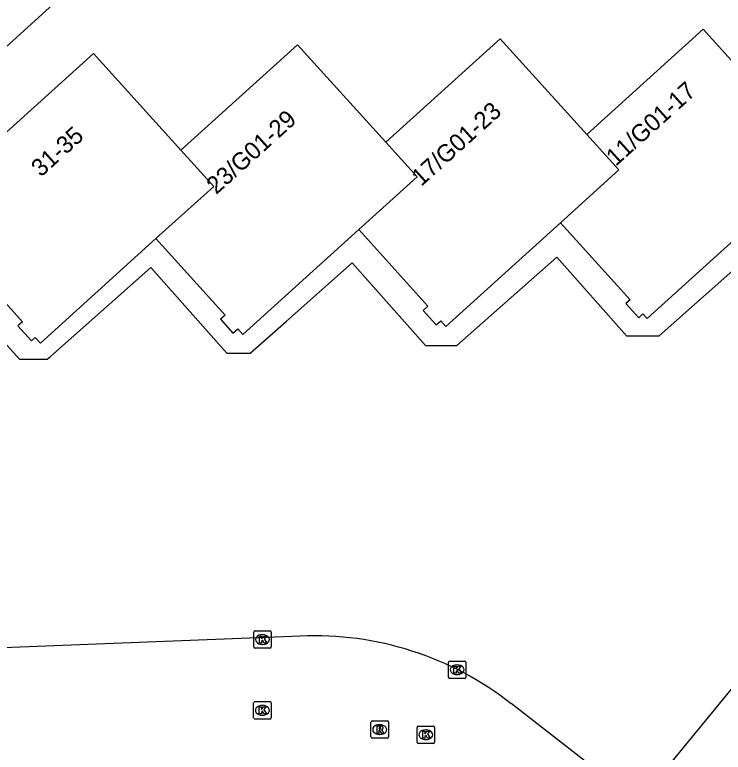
# Model space of a CAD drawing. Extents: x 160356 to 161355, y 381727 to 382845.
# Drawn here: x 160896.38 to 160937.12, y 382011.19 to 382053.61 of the extents above; entities that cross this region are included whole.
import ezdxf

# ---------------------------------------------------------------- set-up
doc = ezdxf.new("R2010")
doc.units = 0
for name, color, linetype in [('IMGEO_Kolk', 7, 'Continuous'), ('IMGEO_Pand', 7, 'Continuous'), ('IMGEO_Pand_nummerreeks', 7, 'Continuous'), ('IMGEO_Rioolput', 7, 'Continuous'), ('IMGEO_Voetpad_halfverhard', 7, 'Continuous'), ('IMGEO_Voetpad_open', 7, 'Continuous')]:
    doc.layers.add(name, color=color, linetype=linetype)

msp = doc.modelspace()

# ---------------------------------------------------------------- linework, layer by layer
at = {"layer": 'IMGEO_Kolk'}
for p, q in [((160910.203, 382018.175), (160911.055, 382018.175)), ((160910.128, 382017.249), (160910.128, 382018.101)), ((160910.616, 382017.955), (160910.641, 382017.955)), ((160911.129, 382018.101), (160911.129, 382017.249)), ((160910.639, 382017.395), (160910.614, 382017.395)), ((160911.055, 382017.175), (160910.203, 382017.175)), ((160921.317, 382015.513), (160921.317, 382016.365)), ((160921.392, 382016.439), (160922.244, 382016.439)), ((160921.805, 382016.219), (160921.83, 382016.219)), ((160922.318, 382016.365), (160922.318, 382015.513)), ((160921.828, 382015.659), (160921.803, 382015.659)), ((160922.244, 382015.439), (160921.392, 382015.439)), ((160910.119, 382013.176), (160910.119, 382014.028)), ((160910.194, 382014.102), (160911.046, 382014.102)), ((160911.12, 382014.028), (160911.12, 382013.176)), ((160910.607, 382013.882), (160910.632, 382013.882)), ((160911.046, 382013.102), (160910.194, 382013.102)), ((160910.63, 382013.322), (160910.605, 382013.322)), ((160919.596, 382012.698), (160920.448, 382012.698)), ((160919.521, 382011.772), (160919.521, 382012.624)), ((160920.009, 382012.478), (160920.034, 382012.478)), ((160920.522, 382012.624), (160920.522, 382011.772)), ((160920.032, 382011.918), (160920.007, 382011.918)), ((160920.448, 382011.698), (160919.596, 382011.698))]:
    msp.add_line(p, q, dxfattribs=at)
for points in [[(160910.203, 382018.175), (160911.055, 382018.175)], [(160910.128, 382017.249), (160910.128, 382018.101)], [(160910.449, 382017.875), (160910.572, 382017.875), (160910.572, 382017.724), (160910.702, 382017.875), (160910.866, 382017.875), (160910.72, 382017.724), (160910.873, 382017.475), (160910.721, 382017.475), (160910.636, 382017.639), (160910.572, 382017.572), (160910.572, 382017.475), (160910.449, 382017.475), (160910.449, 382017.875)], [(160911.129, 382018.101), (160911.129, 382017.249)], [(160911.055, 382017.175), (160910.203, 382017.175)], [(160921.317, 382015.513), (160921.317, 382016.365)], [(160921.392, 382016.439), (160922.244, 382016.439)], [(160921.638, 382016.139), (160921.761, 382016.139), (160921.761, 382015.988), (160921.891, 382016.139), (160922.055, 382016.139), (160921.909, 382015.988), (160922.062, 382015.739), (160921.91, 382015.739), (160921.825, 382015.903), (160921.761, 382015.836), (160921.761, 382015.739), (160921.638, 382015.739), (160921.638, 382016.139)], [(160922.318, 382016.365), (160922.318, 382015.513)], [(160922.244, 382015.439), (160921.392, 382015.439)], [(160910.119, 382013.176), (160910.119, 382014.028)], [(160910.194, 382014.102), (160911.046, 382014.102)], [(160911.12, 382014.028), (160911.12, 382013.176)], [(160910.44, 382013.802), (160910.563, 382013.802), (160910.563, 382013.651), (160910.693, 382013.802), (160910.857, 382013.802), (160910.711, 382013.651), (160910.864, 382013.402), (160910.712, 382013.402), (160910.627, 382013.566), (160910.563, 382013.499), (160910.563, 382013.402), (160910.44, 382013.402), (160910.44, 382013.802)], [(160911.046, 382013.102), (160910.194, 382013.102)], [(160919.596, 382012.698), (160920.448, 382012.698)], [(160919.521, 382011.772), (160919.521, 382012.624)], [(160919.842, 382012.398), (160919.965, 382012.398), (160919.965, 382012.247), (160920.095, 382012.398), (160920.259, 382012.398), (160920.113, 382012.247), (160920.266, 382011.998), (160920.114, 382011.998), (160920.029, 382012.162), (160919.965, 382012.095), (160919.965, 382011.998), (160919.842, 382011.998), (160919.842, 382012.398)], [(160920.522, 382012.624), (160920.522, 382011.772)], [(160920.448, 382011.698), (160919.596, 382011.698)]]:
    msp.add_lwpolyline(points, dxfattribs=at)
for centre, start, end in [((160910.205, 382018.099), 91.552, 178.448), ((160910.205, 382018.099), 91.552, 178.448), ((160911.053, 382018.099), 1.552, 88.448), ((160911.053, 382018.099), 1.552, 88.448), ((160910.205, 382017.251), 181.552, 268.448), ((160910.205, 382017.251), 181.552, 268.448), ((160911.053, 382017.251), 271.552, 358.448), ((160911.053, 382017.251), 271.552, 358.448), ((160921.394, 382016.363), 91.552, 178.448), ((160921.394, 382016.363), 91.552, 178.448), ((160922.242, 382016.363), 1.552, 88.448), ((160922.242, 382016.363), 1.552, 88.448), ((160921.394, 382015.515), 181.552, 268.448), ((160921.394, 382015.515), 181.552, 268.448), ((160922.242, 382015.515), 271.552, 358.448), ((160922.242, 382015.515), 271.552, 358.448), ((160910.196, 382014.026), 91.552, 178.448), ((160910.196, 382014.026), 91.552, 178.448), ((160911.044, 382014.026), 1.552, 88.448), ((160911.044, 382014.026), 1.552, 88.448), ((160910.196, 382013.178), 181.552, 268.448), ((160910.196, 382013.178), 181.552, 268.448), ((160911.044, 382013.178), 271.552, 358.448), ((160911.044, 382013.178), 271.552, 358.448), ((160919.598, 382012.622), 91.552, 178.448), ((160919.598, 382012.622), 91.552, 178.448), ((160920.446, 382012.622), 1.552, 88.448), ((160920.446, 382012.622), 1.552, 88.448), ((160919.598, 382011.774), 181.552, 268.448), ((160919.598, 382011.774), 181.552, 268.448), ((160920.446, 382011.774), 271.552, 358.448), ((160920.446, 382011.774), 271.552, 358.448)]:
    msp.add_arc(centre, 0.0765, start, end, dxfattribs=at)
for centre, major_axis, ratio, start_param, end_param in [((160910.615, 382017.675), (-0.387, 0.002), 0.722429, 4.712389, 7.853982), ((160910.64, 382017.675), (-0.39, 0.002), 0.717154, 1.570796, 4.712389), ((160921.804, 382015.939), (-0.387, 0.002), 0.722429, 4.712389, 7.853982), ((160921.829, 382015.939), (-0.39, 0.002), 0.717154, 1.570796, 4.712389), ((160910.606, 382013.602), (-0.387, 0.002), 0.722429, 4.712389, 7.853982), ((160910.631, 382013.602), (-0.39, 0.002), 0.717154, 1.570796, 4.712389), ((160920.008, 382012.198), (-0.387, 0.002), 0.722429, 4.712389, 7.853982), ((160920.033, 382012.198), (-0.39, 0.002), 0.717154, 1.570796, 4.712389)]:
    msp.add_ellipse(centre, major_axis=major_axis, ratio=ratio, start_param=start_param, end_param=end_param, dxfattribs=at)
at = {"layer": 'IMGEO_Pand'}
for points in [[(160940.987, 382047.227), (160935.969, 382052.777), (160929.276, 382046.726)], [(160929.276, 382046.726), (160924.298, 382052.232), (160917.714, 382046.279)], [(160917.714, 382046.279), (160912.644, 382051.887), (160905.934, 382045.821)], [(160894.271, 382045.393), (160900.902, 382051.387), (160905.934, 382045.821)], [(160929.276, 382046.726), (160931.124, 382044.682), (160927.77, 382041.649)], [(160916.161, 382041.251), (160919.517, 382044.285), (160917.714, 382046.279)], [(160905.934, 382045.821), (160907.821, 382043.734), (160904.5, 382040.732)], [(160927.77, 382041.649), (160931.774, 382037.22), (160931.526, 382036.997), (160932.26, 382036.184), (160932.505, 382036.406), (160932.74, 382036.146), (160939.562, 382042.313)], [(160916.161, 382041.251), (160920.138, 382036.852), (160919.861, 382036.601), (160920.614, 382035.769), (160920.882, 382036.011), (160921.175, 382035.687), (160927.77, 382041.649)], [(160904.5, 382040.732), (160908.474, 382036.337), (160908.207, 382036.095), (160908.93, 382035.296), (160909.207, 382035.546), (160909.497, 382035.225), (160916.161, 382041.251)], [(160892.87, 382040.319), (160896.818, 382035.953), (160896.561, 382035.72), (160897.346, 382034.851), (160897.565, 382035.049), (160897.857, 382034.726), (160904.5, 382040.732)]]:
    msp.add_lwpolyline(points, dxfattribs=at)
at = {"layer": 'IMGEO_Rioolput'}
for p, q in [((160916.866, 382012.071), (160916.866, 382012.923)), ((160916.941, 382012.997), (160917.793, 382012.997)), ((160917.354, 382012.777), (160917.379, 382012.777)), ((160917.867, 382012.923), (160917.867, 382012.071)), ((160917.377, 382012.217), (160917.352, 382012.217)), ((160917.793, 382011.997), (160916.941, 382011.997))]:
    msp.add_line(p, q, dxfattribs=at)
for points in [[(160916.866, 382012.071), (160916.866, 382012.923)], [(160916.941, 382012.997), (160917.793, 382012.997)], [(160917.455, 382012.695), (160917.203, 382012.697), (160917.203, 382012.297)], [(160917.867, 382012.923), (160917.867, 382012.071)], [(160917.203, 382012.297), (160917.327, 382012.297), (160917.327, 382012.459), (160917.338, 382012.459)], [(160917.381, 382012.616), (160917.327, 382012.616), (160917.327, 382012.535)], [(160917.327, 382012.535), (160917.379, 382012.535)], [(160917.385, 382012.43), (160917.456, 382012.297), (160917.596, 382012.297), (160917.531, 382012.423)], [(160917.793, 382011.997), (160916.941, 382011.997)]]:
    msp.add_lwpolyline(points, dxfattribs=at)
for centre, radius, start, end in [((160916.943, 382012.921), 0.0765, 91.552, 178.448), ((160916.943, 382012.921), 0.0765, 91.552, 178.448), ((160917.454, 382012.585), 0.109, 350.3612, 89.416), ((160917.791, 382012.921), 0.0765, 1.552, 88.448), ((160917.791, 382012.921), 0.0765, 1.552, 88.448), ((160917.337, 382012.406), 0.0533, 26.0293, 88.6989), ((160917.363, 382012.724), 0.19, 274.7715, 282.9687), ((160917.387, 382012.52), 0.0964, 77.0061, 93.1865), ((160917.401, 382012.577), 0.0378, 276.6634, 79.6772), ((160917.452, 382012.585), 0.112, 277.5842, 350.9817), ((160917.436, 382012.37), 0.108, 29.5134, 73.7905), ((160916.943, 382012.073), 0.0765, 181.552, 268.448), ((160916.943, 382012.073), 0.0765, 181.552, 268.448), ((160917.791, 382012.073), 0.0765, 271.552, 358.448), ((160917.791, 382012.073), 0.0765, 271.552, 358.448)]:
    msp.add_arc(centre, radius, start, end, dxfattribs=at)
for centre, major_axis, ratio, start_param, end_param in [((160917.353, 382012.497), (-0.387, 0.002), 0.722429, 4.712389, 7.853982), ((160917.378, 382012.497), (-0.39, 0.002), 0.717154, 1.570796, 4.712389)]:
    msp.add_ellipse(centre, major_axis=major_axis, ratio=ratio, start_param=start_param, end_param=end_param, dxfattribs=at)
at = {"layer": 'IMGEO_Voetpad_halfverhard'}
msp.add_lwpolyline([(160892.401, 382038.504), (160896.66, 382033.793), (160898.252, 382033.793), (160898.44, 382033.96), (160904.216, 382039.071), (160908.582, 382034.138), (160909.917, 382034.138), (160912.011, 382035.992), (160915.79, 382039.336), (160919.995, 382034.585), (160921.802, 382034.585), (160927.547, 382039.669), (160931.554, 382035.143), (160933.429, 382035.143), (160939.368, 382040.398), (160943.61, 382035.605), (160945.564, 382035.605), (160948.337, 382037.416), (160949.99, 382038.593), (160951.416, 382039.751), (160952.367, 382040.662), (160954.013, 382042.847), (160955.293, 382044.719)], dxfattribs=at)
at = {"layer": 'IMGEO_Voetpad_open'}
for points in [[(160885.684, 382056.644), (160893.142, 382049.287), (160900.452, 382055.921), (160900.735, 382056.178), (160899.618, 382057.218)], [(160958.918, 382040.842), (160932.496, 382008.634), (160932.226, 382008.305)], [(160912.804, 382017.876), (160886.414, 382016.842)], [(160932.226, 382008.305), (160924.933, 382013.986)]]:
    msp.add_lwpolyline(points, dxfattribs=at)
msp.add_arc((160913.597, 381999.493), 18.4, 51.9668, 92.4692, dxfattribs=at)

# ---------------------------------------------------------------- texts
at = {"layer": 'IMGEO_Pand_nummerreeks'}
for s, rotation, p in [('11/G01-17', 42.1161, (160930.942, 382044.862)), ('17/G01-23', 42.1187, (160919.753, 382043.701)), ('23/G01-29', 42.1143, (160907.966, 382043.236)), ('31-35', 42.1116, (160897.885, 382044.238))]:
    msp.add_text(s, height=1, rotation=rotation, dxfattribs=at).set_placement(p)

doc.saveas('drawing.dxf')
